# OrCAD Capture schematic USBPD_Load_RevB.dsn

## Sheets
1 Title: title: USB Power Delivery Load Board; rev: 0.1; company: ON SEMICONDUCTOR - NWSEC; note: ONSEC-16-004; note: 9000 SW Gemini Dr.; note: Beaverton, OR 97008
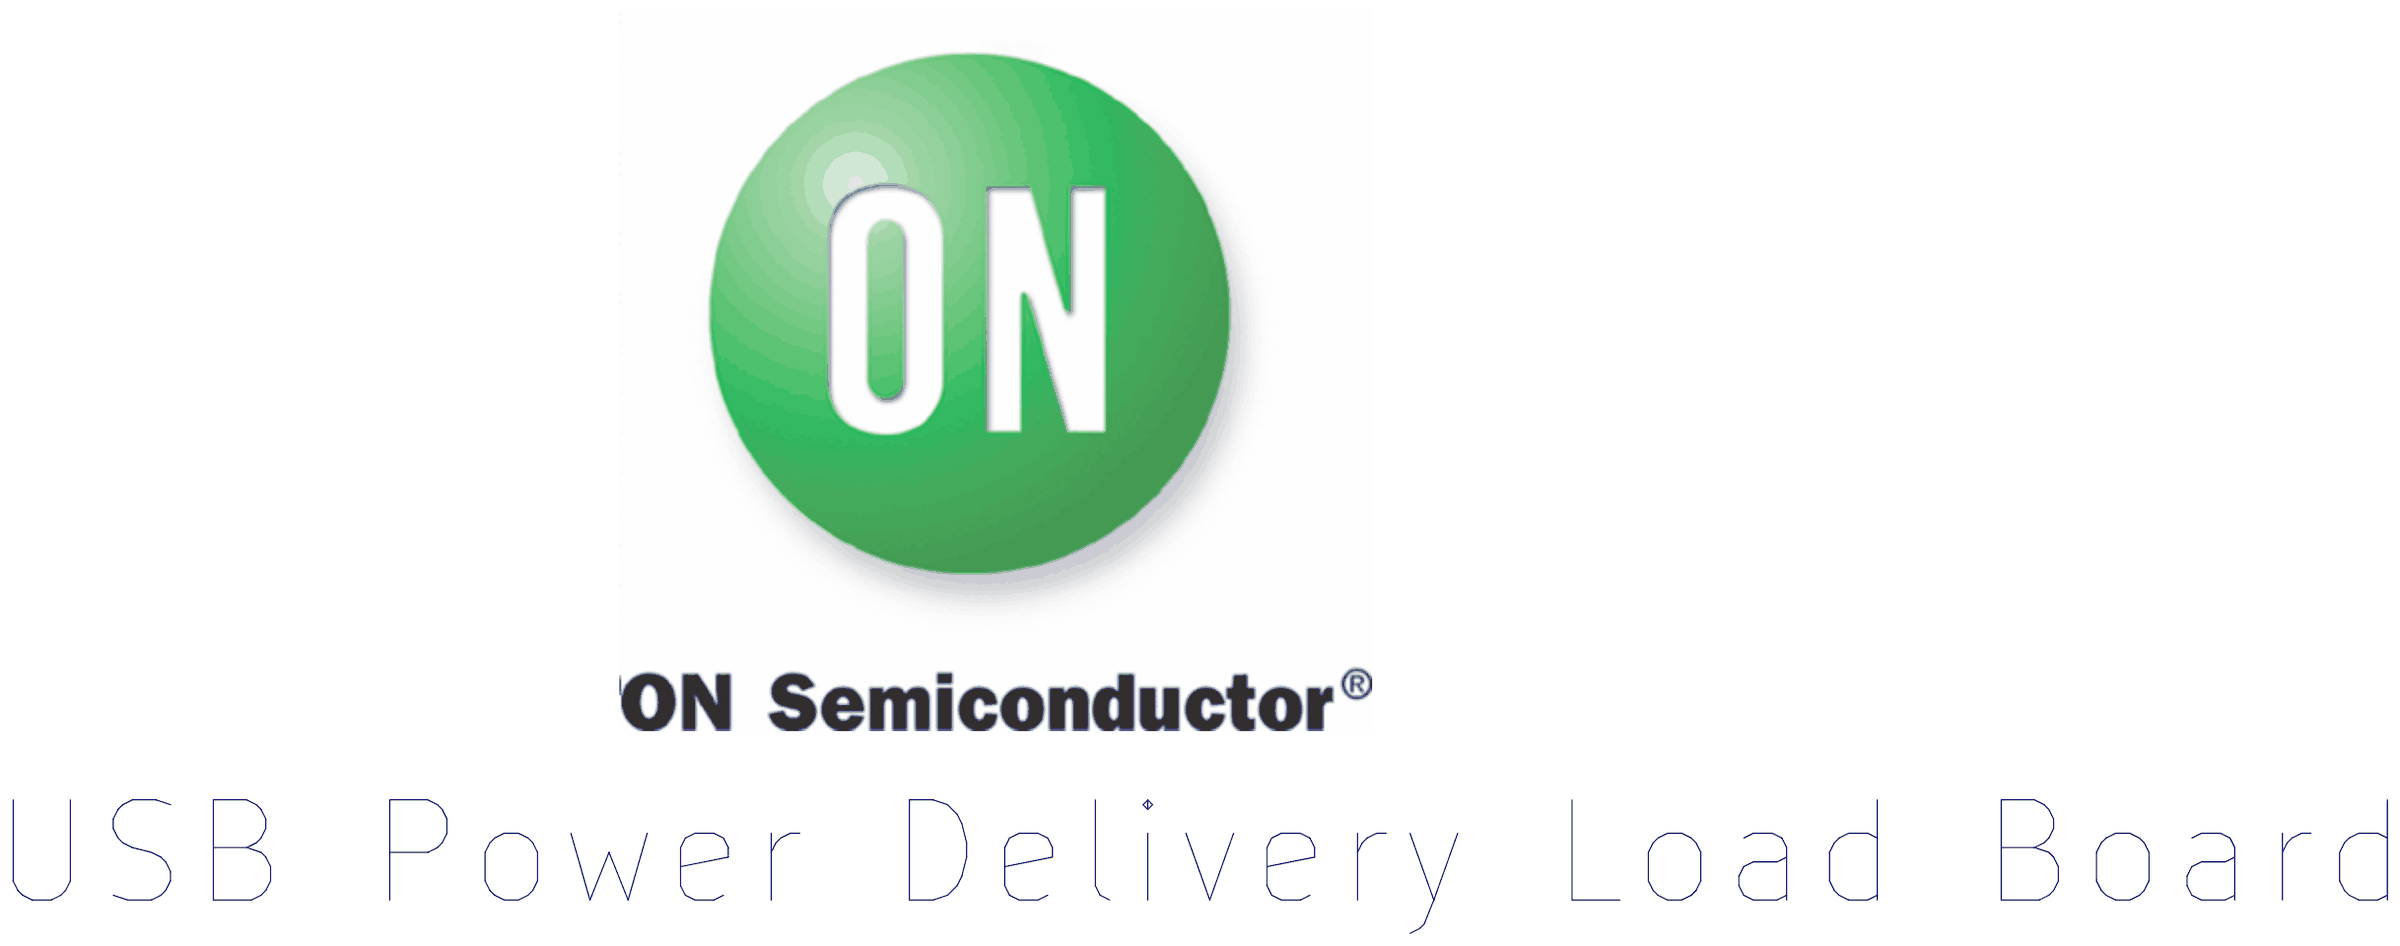
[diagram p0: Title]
2 Schematic: size Custom
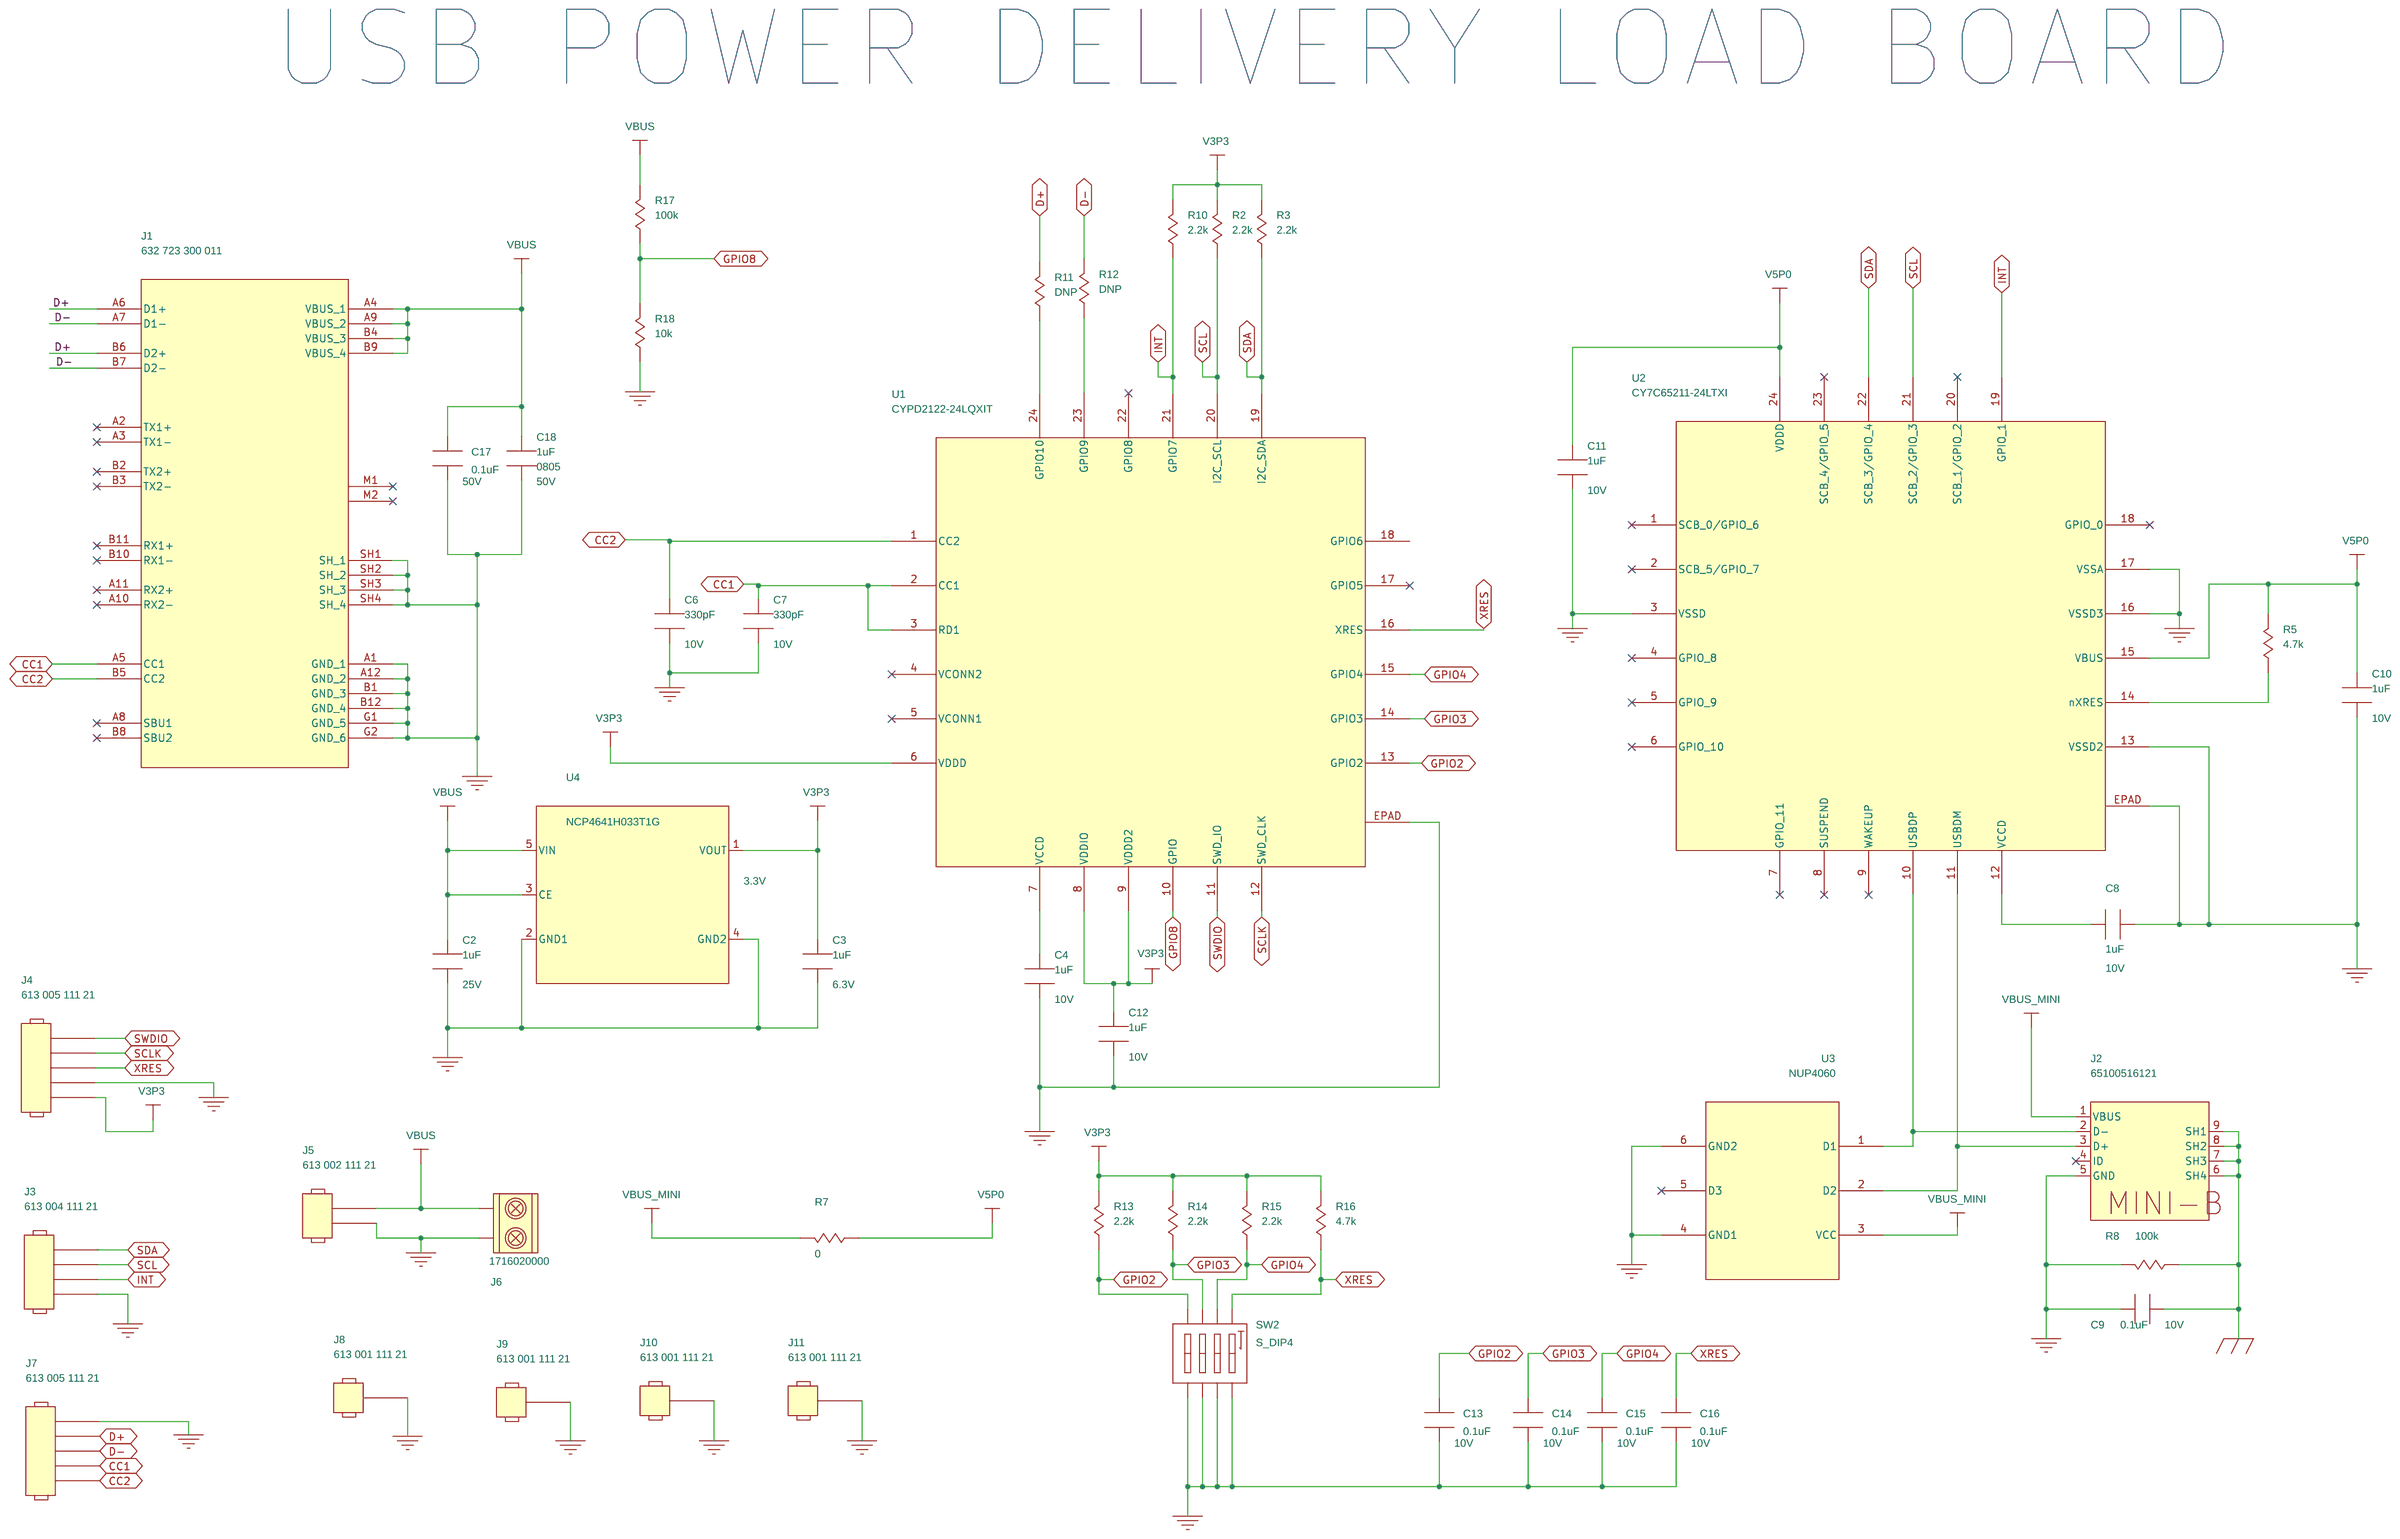
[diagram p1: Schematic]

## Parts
C2  1uF  [SMC0603]
C3  1uF  [SMC0603]
C4  1uF  [SMC0603]
C6  330pF  [SMC0603]
C7  330pF  [SMC0603]
C8  1uF  [SMC0603]
C9  0.1uF  [SMC0603]
C10  1uF  [SMC0603]
C11  1uF  [SMC0603]
C12  1uF  [SMC0603]
C13  0.1uF  [SMC0603]
C14  0.1uF  [SMC0603]
C15  0.1uF  [SMC0603]
C16  0.1uF  [SMC0603]
C17  0.1uF  [SMC0603]
C18  1uF  [SMC0805]
J1  632 723 300 011  [Wurth_USBPD_Type_C]
J2  65100516121  [con_miniusb2-stnd_B]
J3  613 004 111 21  [jthi_hdr1r4ps_100mil]
J4  613 005 111 21  [jthi_hdr1r5ps_100mil]
J5  613 002 111 21  [jthi_hdr1r2ps_100mil]
J6  1716020000  [Weidmuller-171602000]
J7  613 005 111 21  [jthi_hdr1r5ps_100mil]
J8  613 001 111 21  [jthi_hdr1r1ps_100mil]
J9  613 001 111 21  [jthi_hdr1r1ps_100mil]
J10  613 001 111 21  [jthi_hdr1r1ps_100mil]
J11  613 001 111 21  [jthi_hdr1r1ps_100mil]
R2  2.2k  [smr0603]
R3  2.2k  [smr0603]
R5  4.7k  [smr0603]
R7  0  [smr0603]
R8  100k  [smr0603]
R10  2.2k  [smr0603]
R11  DNP  [smr0603]
R12  DNP  [smr0603]
R13  2.2k  [smr0603]
R14  2.2k  [smr0603]
R15  2.2k  [smr0603]
R16  4.7k  [smr0603]
R17  100k  [smr0603]
R18  10k  [smr0603]
SW2  S_DIP4  [sthi_dip04]
U1  CYPD2122-24LQXIT  [usmm_qfn24r4x4_0p5_ep_rwk]
U2  CY7C65211-24LTXI  [usmm_qfn24r4x4_0p5_ep_rwk]
U3  NUP4060  [SOT-563-6]
U4  NCP4641H033T1G  [sot89-5]

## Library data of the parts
C2 = 0603_v2: Voltage: 25V
C3 = 0603_v2: Voltage: 6.3V
C4 C6-C16 = 0603_v2: Voltage: 10V
C17 = 0603_v2: Voltage: 50V
C18 = CAP_NP: Generic 0805 SMD Capacitor; Height: 1.35; Package: 0805; Voltage: 50V
J1 = 632723300011_USB3_1_C_PD
J2 = 65100516121_Mini_USB1_2_B
J3 = 613_004_111_21_1x4_100mil
J4 J7 = 613_005_111_21_1x5_100mil
J5 = 613_002_111_21_1x2_100mil: Silkscreen: VBUS
J6 = 1716020000_2pin_Screw: MFR: Wurth; MFRPN: 691216510002S; Silkscreen: VBUS
J8-J11 = 613_001_111_21_1x1_100mil: Silkscreen: GND
R2 R3 R5 R7 R8 R10-R18 = 0603
SW2 = 206-4
U1 = CYPD21XX-24LQXIT
U2 = CY7C65211-24LTXI
U3 = CM1240
U4 = NCP1450-PWM_StepUp_CNTRL_2: LDO NCP4641H050T1G; Manufacturer PN: NCP4641H050T1G; VOUT: 3.3V

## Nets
GND: C2.2 C3.2 C4.2 C6.2 C7.2 C8.2 C9.1 C10.2 C11.2 C12.2 C13.1 C14.1 C15.1 C16.1 C17.1 C18.2 J1.A1(GND_1) J1.A12(GND_2) J1.B1(GND_3) J1.B12(GND_4) J1.G1(GND_5) J1.G2(GND_6) J1.SH1(SH_1) J1.SH2(SH_2) J1.SH3(SH_3) J1.SH4(SH_4) J2.5(GND) J3.4 J4.4 J5.2 J6.1 J7.1 J8.1 J9.1 J10.1 J11.1 R8.1 R18.2 SW2.5 SW2.6 SW2.7 SW2.8 U1.EPAD U2.3(VSSD) U2.13(VSSD2) U2.16(VSSD3) U2.17(VSSA) U2.EPAD U3.4(GND1) U3.6(GND2) U4.2(GND1) U4.4(GND2)
GND_EARTH: C9.2 J2.6(SH4) J2.7(SH3) J2.8(SH2) J2.9(SH1) R8.2
V3P3: C3.1 C12.1 J4.5 R2.1 R3.1 R10.1 R13.1 R14.1 R15.1 R16.1 U1.6(VDDD) U1.8(VDDIO) U1.9(VDDD2) U4.1(VOUT)
V5P0: C10.1 C11.1 R5.1 R7.2 U2.15(VBUS) U2.24(VDDD)
VBUS: C2.1 C17.2 C18.1 J1.A4(VBUS_1) J1.A9(VBUS_2) J1.B4(VBUS_3) J1.B9(VBUS_4) J5.1 J6.2 R17.1 U4.3(CE) U4.5(VIN)
VBUS_MINI: J2.1(VBUS) R7.1 U3.3(VCC)
CC1: C7.1 J1.A5(CC1) J7.4 U1.2(CC1) U1.3(RD1)
CC2: C6.1 J1.B5(CC2) J7.5 U1.1(CC2)
D+: J1.A6(D1+) J1.B6(D2+) J7.2 R11.1
D-: J1.A7(D1-) J1.B7(D2-) J7.3 R12.1
GPIO2: C13.2 R13.2 SW2.4 U1.13(GPIO2)
GPIO3: C14.2 R14.2 SW2.3 U1.14(GPIO3)
GPIO4: C15.2 R15.2 SW2.2 U1.15(GPIO4)
GPIO8: R17.2 R18.1 U1.10(GPIO)
INT: J3.3 R10.2 U1.21(GPIO7) U2.19(GPIO_1)
SCL: J3.2 R2.2 U1.20(I2C_SCL) U2.21(SCB_2/GPIO_3)
SCLK: J4.2 U1.12(SWD_CLK)
SDA: J3.1 R3.2 U1.19(I2C_SDA) U2.22(SCB_3/GPIO_4)
SWDIO: J4.1 U1.11(SWD_IO)
XRES: C16.2 J4.3 R16.2 SW2.1 U1.16(XRES)
N13979004: J2.2(D-) U2.10(USBDP) U3.1(D1)
N13979011: J2.3(D+) U2.11(USBDM) U3.2(D2)
N13982640: C4.1 U1.7(VCCD)
N13984820: R5.2 U2.14(nXRES)
N13984928: C8.1 U2.12(VCCD)
N14015838: R11.2 U1.24(GPIO10)
N14015876: R12.2 U1.23(GPIO9)

Not connected (* = marked no-connect by the designer): J1 A2(TX1+)* A3(TX1-)* A8(SBU1)* A10(RX2-)* A11(RX2+)* B2(TX2+)* B3(TX2-)* B8(SBU2)* B10(RX1-)* B11(RX1+)* M1* M2*; J2 4(ID)*; U1 4(VCONN2)* 5(VCONN1)* 17(GPIO5)* 18(GPIO6) 22(GPIO8)*; U2 1(SCB_0/GPIO_6)* 2(SCB_5/GPIO_7)* 4(GPIO_8)* 5(GPIO_9)* 6(GPIO_10)* 7(GPIO_11)* 8(SUSPEND)* 9(WAKEUP)* 18(GPIO_0)* 20(SCB_1/GPIO_2)* 23(SCB_4/GPIO_5)*; U3 5(D3)*

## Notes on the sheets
sheet 1
- USB Power Delivery Load Board
sheet 2
- USB POWER DELIVERY LOAD BOARD
